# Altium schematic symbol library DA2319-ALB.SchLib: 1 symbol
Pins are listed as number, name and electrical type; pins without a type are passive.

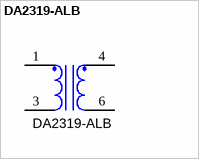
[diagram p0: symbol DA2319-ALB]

## DA2319-ALB
designator X?
Manufacturer: Coilcraft; SymbolVersion: use current date i.e. 2008-05-20; SymbolCreator: Use a-id; CompType: Transformer; U/M: EA
pins: 1, 3, 4, 6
